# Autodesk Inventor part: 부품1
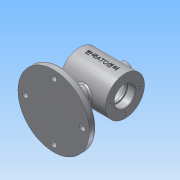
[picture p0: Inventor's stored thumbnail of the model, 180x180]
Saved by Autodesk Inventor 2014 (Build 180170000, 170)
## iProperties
Created: 2018-12
Part Number: 부품1
Material: 알루미늄 6061
Document SubType Name: Modeling
Designer: 601-06
Density: 2.71 g/cm^3
Appearance: 알루미늄 - 평지
Author: 601-06
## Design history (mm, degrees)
sketch "스케치1"
  geometry: L1 (0, 0)-(55, 0); L2 (55, 0)-(55, 10); L3 (55, 10)-(12, 21.522); L4 (12, 21.522)-(0, 21.522); L5 (0, 21.522)-(0, 0)
  constraints: 10 end point, 2 perpendicular, 1 horizontal, 1 parallel
  dimensions: "d1" = 55 distance between parallel lines of L2 L5; "d2" = 10 distance of L1.end L2.end; "d3" = 75 deg angle of L3 L2; "d4" = 12 distance of L3.end L4.end
revolve "회전1" sketch "스케치1" stored, may be unused: angle "d5" = 90 deg
sketch "스케치2" dims "d6" = 88
  geometry: L1 (0, 0)-(52.076, 0); C1 r 55 at (0, 0) reference; 3 further points
  constraints: 3 coincident, 2 end point, 1 horizontal, 1 horizontal alignment, 1 point on line, 2 other
hole "구멍1" sketch "스케치2" at (44, 0) diameter "d7" = 9; stored, may be unused: countersink angle "d11" = 90 deg, drill point angle "d13" = 0 deg; dims "d8" = 6, "d9" = 4, "d10" = 2, "d12" = 10
sketch "스케치4"
  geometry: C1 r 12 at (0, 0) reference; 1 further point
hole "구멍2" sketch "스케치4" at (44, 0) diameter "d19" = 14; stored, may be unused: countersink angle "d23" = 90 deg, drill point angle "d25" = 0 deg; dims "d20" = 6, "d21" = 4, "d22" = 2, "d24" = 11.522
sketch "스케치5"
  geometry: L1 (-35, 75)-(35, 75); L2 (-55, 0)-(55, 0) reference; L3 (-35, 105)-(35, 105); L4 (35, 75)-(35, 105); L5 (-35, 75)-(-35, 105); 1 further point
  constraints: 8 end point, 2 parallel, 1 horizontal, 1 perpendicular
  dimensions: "d31" = 60 diameter of L3 L1; "d34" = 70 distance between parallel lines of L4 L5; "d36" = 75 distance between parallel lines of L2 L1
revolve "회전2" sketch "스케치5" stored, may be unused: angle "d37" = 90 deg
sketch "스케치6"
  geometry: L1 (42.426, -65)-(42.426, -75) reference; L2 (42.426, -75)-(-42.426, -75) reference; L3 (-42.426, -75)-(-42.426, -65) reference; C1 r 30 at (0, 0) reference; 3 further points
  constraints: 1 coincident, 1 horizontal alignment
  node "절단 모서리 투영2"
hole "구멍3" sketch "스케치6" diameter "d39" = 28; stored, may be unused: countersink angle "d43" = 90 deg, drill point angle "d45" = 0 deg; dims "d40" = 6, "d41" = 32, "d42" = 12, "d44" = 15
hole "구멍4" sketch "스케치6" diameter "d46" = 3.242; stored, may be unused: countersink angle "d50" = 90 deg, drill point angle "d52" = 118 deg; dims "d47" = 8, "d48" = 32, "d49" = 12, "d51" = 10
sketch "스케치7"
  geometry: C1 r 14 at (0, 0) reference; 2 further points
  constraints: 1 coincident
hole "구멍5" sketch "스케치7" diameter "d56" = 50; stored, may be unused: countersink angle "d60" = 90 deg, drill point angle "d62" = 0 deg; dims "d57" = 8, "d58" = 32, "d59" = 12, "d61" = 20
node "작업 평면1"
sketch "스케치8"
  geometry: C1 r 12 at (0, 0) reference
sketch "스케치9"
  geometry: C1 r 12 at (0, 0) reference; C2 r 12 at (0, 0)
  constraints: 1 centre point, 1 coincident
  dimensions: "d63" = 24 diameter of C2
extrude "돌출1" join sketch "스케치8" stored distance "d64" = 10; taper "d65" = 0 deg
fillet "모깎기1" dims "d66" = 3
node "작업 평면2"
sketch "스케치10"
  geometry: C1 r 10 at (0, 0); 1 further point
  constraints: 1 centre point, 1 coincident
  dimensions: "d67" = 20 diameter of C1
extrude "돌출2" join sketch "스케치10" stored distance "d68" = 14; taper "d69" = 0 deg
hole "구멍6" sketch "스케치7" diameter "d70" = 50; stored, may be unused: countersink angle "d74" = 90 deg, drill point angle "d76" = 0 deg; dims "d71" = 8, "d72" = 32, "d73" = 12, "d75" = 40
fillet "모깎기2" dims "d77" = 3
sketch "스케치11"
  geometry: C1 r 10 at (0, 0) reference; 1 further point
  constraints: 1 coincident
hole "구멍7" sketch "스케치11" at (0, 0) diameter "d78" = 10; stored, may be unused: countersink angle "d82" = 90 deg, drill point angle "d84" = 0 deg; dims "d79" = 8, "d80" = 32, "d81" = 12, "d83" = 30
chamfer "모따기1" distance "d85" = 1; stored, may be unused: second distance "d86" = 2, angle "d87" = 45 deg
fillet "모깎기3" dims "d88" = 3
fillet "모깎기4" dims "d89" = 0.3
fillet "모깎기5" dims "d90" = 1
node "작업 평면3"
sketch "스케치12"
  geometry: 1 further point
node "작업 평면6"
sketch "스케치15"
  geometry: 1 further point
node "작업 평면8"
sketch "스케치16"
  geometry: L1 (-35, 0)-(35, 0) reference; L2 (46.098, -67.302)-(46.098, -75) reference; L3 (46.098, -75)-(-46.098, -75) reference; L4 (-46.098, -75)-(-46.098, -67.302) reference; 5 further points
  constraints: 1 coincident, 1 horizontal alignment, 1 midpoint, 3 other
feature "엠보싱1" sketch "스케치16" dims "d1" = 55, "d2" = 10, "d3" = 75 deg, "d4" = 12, "d93" = 0.5, "d94" = 0
node "솔리드1"
pattern_circular "원형 패턴1" dims angle "d15" = 360 deg
pattern_circular "원형 패턴2" dims angle "d27" = 360 deg
pattern_circular "원형 패턴3" dims angle "d54" = 360 deg
mirror "대칭1"
mirror "대칭2"
node "절단 모서리 투영1"
node "절단 모서리 투영3"
